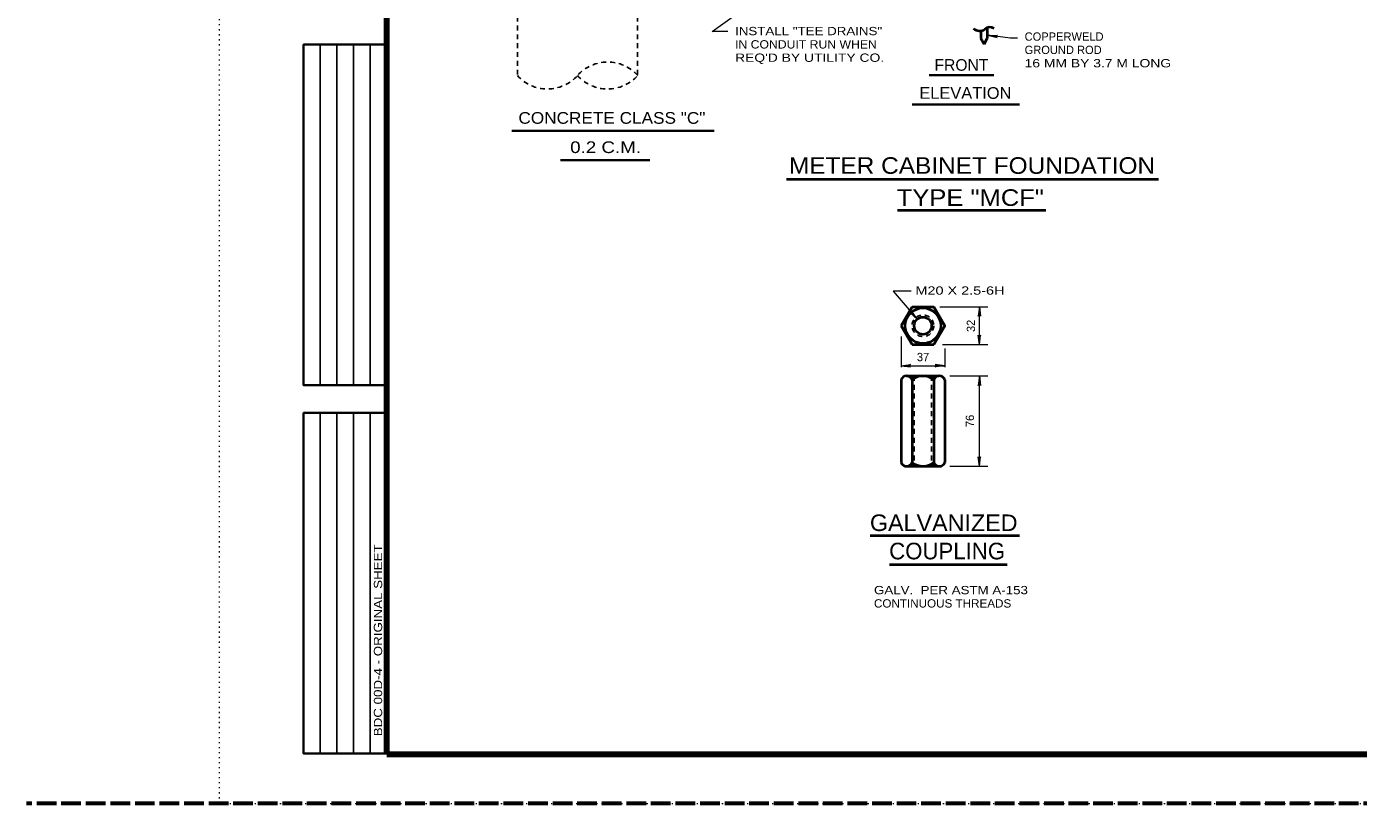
# Model space of a CAD drawing. Extents: x 312583 to 312854, y 144419 to 144597.
# Drawn here: x 312583.5 to 312705.5, y 144418.6 to 144489.8 of the extents above; entities that cross this region are included whole.
import ezdxf
from ezdxf.enums import TextEntityAlignment as Align

# ---------------------------------------------------------------- set-up
doc = ezdxf.new("R2010")
doc.units = 0
doc.header["$LTSCALE"] = 0.3
for name, pattern in [('DOTTED', [1.5, 0.3, -1.2]), ('LONG_DASHED', [7.5, 6, -1.5]), ('SHORT_DASHED', [2.7, 1.5, -1.2])]:
    doc.linetypes.add(name, pattern=pattern)
for name, color, linetype, lineweight in [('1', 7, 'Continuous', 25), ('2', 7, 'Continuous', 13), ('62', 7, 'DOTTED', 13), ('63', 7, 'LONG_DASHED', 60)]:
    doc.layers.add(name, color=color, linetype=linetype, lineweight=lineweight)

msp = doc.modelspace()

# ---------------------------------------------------------------- linework, layer by layer
at = {"layer": '1', "lineweight": 40}
for p, q in [((312670.8996, 144489.375), (312670.8996, 144488.6773)), ((312671.4976, 144489.6586), (312671.4976, 144488.6773)), ((312663.6128, 144462.3613), (312664.6095, 144464.0863)), ((312664.6095, 144464.0863), (312666.6028, 144464.0863)), ((312664.6095, 144460.6363), (312663.6128, 144462.3613)), ((312664.6095, 144460.6363), (312666.6028, 144460.6363)), ((312664.1111, 144457.7537), (312667.0551, 144457.7537)), ((312663.6128, 144457.4087), (312663.6128, 144449.8187)), ((312664.6171, 144457.4087), (312664.6171, 144449.8187)), ((312666.6028, 144457.4087), (312666.6028, 144449.8187)), ((312667.5995, 144457.4087), (312667.5995, 144449.8187)), ((312664.1111, 144449.4737), (312667.0551, 144449.4737)), ((312664.1111, 144449.4737), (312667.0551, 144449.4737))]:
    msp.add_line(p, q, dxfattribs=at)
at = {"layer": '1'}
for p, q in [((312610.4087, 144456.901), (312610.4087, 144488.1192)), ((312611.9315, 144456.901), (312611.9315, 144488.1192)), ((312613.4543, 144456.901), (312613.4543, 144488.1192)), ((312614.9772, 144456.901), (312614.9772, 144488.1192)), ((312610.4087, 144423.1446), (312610.4087, 144454.3629)), ((312611.9315, 144423.1446), (312611.9315, 144454.3629)), ((312613.4543, 144423.1446), (312613.4543, 144454.3629)), ((312614.9772, 144423.1446), (312614.9772, 144454.3629))]:
    msp.add_line(p, q, dxfattribs=at)
at = {"layer": '1', "linetype": 'SHORT_DASHED'}
for p, q in [((312664.8088, 144457.7537), (312664.8088, 144449.4737)), ((312666.4035, 144457.7537), (312666.4035, 144449.4737))]:
    msp.add_line(p, q, dxfattribs=at)
at = {"layer": '1', "lineweight": 158}
msp.add_line((312616.5, 144423.0846), (312849, 144423.0846), dxfattribs=at)
msp.add_lwpolyline([(312616.5, 144423.1446), (312616.5, 144585.0846), (312849, 144585.0846)], dxfattribs=at)
at = {"layer": '1', "lineweight": 35}
for points in [[(312616.5, 144456.901), (312608.8858, 144456.901), (312608.8858, 144488.1192), (312616.5, 144488.1192)], [(312616.5, 144423.1446), (312608.8858, 144423.1446), (312608.8858, 144454.3629), (312616.5, 144454.3629)]]:
    msp.add_lwpolyline(points, dxfattribs=at)
at = {"layer": '1', "lineweight": 40}
for points in [[(312666.6028, 144460.6363), (312667.5995, 144462.3613), (312666.6028, 144464.0863)], [(312664.2645, 144457.746), (312665.3378, 144457.7537), (312665.1155, 144457.7), (312664.8625, 144457.5927), (312664.6325, 144457.4393), (312664.5481, 144457.5543), (312664.4485, 144457.6617), (312664.3258, 144457.723), (312665.1768, 144457.7383), (312664.9775, 144457.677), (312664.8088, 144457.5773), (312664.6401, 144457.4777), (312664.5788, 144457.5467), (312664.4561, 144457.6693), (312664.3948, 144457.7), (312665.0618, 144457.723), (312664.6478, 144457.5083), (312664.4868, 144457.6693), (312664.9698, 144457.7), (312664.6478, 144457.539), (312664.5405, 144457.6617), (312664.8931, 144457.6847), (312664.6555, 144457.5697), (312664.5941, 144457.6463), (312664.7628, 144457.654), (312664.6555, 144457.608), (312664.6555, 144457.6463), (312664.7168, 144457.6387)], [(312666.9478, 144457.746), (312665.8821, 144457.7537), (312666.1045, 144457.7), (312666.3498, 144457.5927), (312666.5875, 144457.4393), (312666.6718, 144457.5543), (312666.7715, 144457.6617), (312666.8865, 144457.723), (312666.0355, 144457.7383), (312666.2348, 144457.677), (312666.4035, 144457.5773), (312666.5721, 144457.4777), (312666.6335, 144457.5467), (312666.7561, 144457.6693), (312666.8175, 144457.7), (312666.1581, 144457.723), (312666.5721, 144457.5083), (312666.7331, 144457.6693), (312666.2501, 144457.7), (312666.5721, 144457.539), (312666.6718, 144457.6617), (312666.3268, 144457.6847), (312666.5645, 144457.5697), (312666.6181, 144457.6463), (312666.4571, 144457.654), (312666.5568, 144457.608), (312666.5645, 144457.6463), (312666.4955, 144457.6387)], [(312664.2645, 144449.489), (312665.3378, 144449.4813), (312665.1155, 144449.535), (312664.8625, 144449.6423), (312664.6325, 144449.7957), (312664.5481, 144449.6807), (312664.4485, 144449.5733), (312664.3258, 144449.5043), (312665.1768, 144449.4967), (312664.9775, 144449.558), (312664.8088, 144449.65), (312664.6401, 144449.7497), (312664.5788, 144449.6807), (312664.4561, 144449.5657), (312664.3948, 144449.535), (312665.0618, 144449.512), (312664.6478, 144449.7267), (312664.4868, 144449.5657), (312664.9698, 144449.535), (312664.6478, 144449.696), (312664.5405, 144449.5733), (312664.8931, 144449.5503), (312664.6555, 144449.6653), (312664.5941, 144449.581), (312664.7628, 144449.581), (312664.6555, 144449.627), (312664.6555, 144449.581), (312664.7168, 144449.5963)], [(312666.9478, 144449.489), (312665.8821, 144449.4813), (312666.1045, 144449.535), (312666.3498, 144449.6423), (312666.5875, 144449.7957), (312666.6718, 144449.6807), (312666.7715, 144449.5733), (312666.8865, 144449.5043), (312666.0355, 144449.4967), (312666.2348, 144449.558), (312666.4035, 144449.65), (312666.5721, 144449.7497), (312666.6335, 144449.6807), (312666.7561, 144449.5657), (312666.8175, 144449.535), (312666.1581, 144449.512), (312666.5721, 144449.7267), (312666.7331, 144449.5657), (312666.2501, 144449.535), (312666.5721, 144449.696), (312666.6718, 144449.5733), (312666.3268, 144449.5503), (312666.5645, 144449.6653), (312666.6181, 144449.581), (312666.4571, 144449.581), (312666.5568, 144449.627), (312666.5645, 144449.581), (312666.4955, 144449.5963)]]:
    msp.add_lwpolyline(points, dxfattribs=at)
for radius in [1.6267, 0.7949]:
    msp.add_circle((312665.6072, 144462.3583), radius, dxfattribs=at)
at = {"layer": '1', "linetype": 'SHORT_DASHED'}
msp.add_circle((312665.6072, 144462.3583), 0.9936, dxfattribs=at)
at = {"layer": '1', "lineweight": 40}
for centre, radius, start, end in [((312670.8004, 144490.1751), 0.8027, 225.84295, 305.84934), ((312671.7467, 144488.9938), 0.713, 58.11032, 131.90694), ((312664.114, 144457.223), 0.5342, 20.74148, 159.25852), ((312665.6072, 144456.1539), 1.6033, 51.70372, 128.29627), ((312667.1003, 144457.223), 0.5342, 20.74148, 159.25852), ((312664.114, 144450.0113), 0.5342, 200.74148, 339.25852), ((312665.6072, 144451.0804), 1.6033, 231.70372, 308.29627), ((312667.1003, 144450.0113), 0.5342, 200.74148, 339.25852)]:
    msp.add_arc(centre, radius, start, end, dxfattribs=at)
at = {"layer": '1', "linetype": 'SHORT_DASHED'}
for centre, start, end in [((312636.7283, 144482.8473), 41.50958, 138.49042), ((312631.2179, 144487.7242), 221.50958, 318.49042), ((312636.7283, 144487.7242), 221.50958, 318.49042)]:
    msp.add_arc(centre, 3.6793, start, end, dxfattribs=at)
at = {"layer": '2', "linetype": 'SHORT_DASHED', "lineweight": 25}
for p, q in [((312628.4646, 144517.4043), (312628.4646, 144485.2886)), ((312639.4816, 144517.4043), (312639.4816, 144485.2886))]:
    msp.add_line(p, q, dxfattribs=at)
at = {"layer": '2'}
for p, q in [((312646.2896, 144489.329), (312651.1273, 144492.802)), ((312647.7463, 144489.329), (312646.2896, 144489.329)), ((312671.559, 144488.9686), (312672.4023, 144488.754)), ((312671.559, 144488.9686), (312672.433, 144488.961)), ((312672.433, 144488.961), (312672.1493, 144488.892)), ((312672.4023, 144488.754), (312672.1493, 144488.892)), ((312664.4408, 144463.542), (312664.7015, 144463.404)), ((312665.0848, 144462.9593), (312664.4408, 144463.542)), ((312664.6018, 144463.6877), (312664.7015, 144463.404)), ((312665.0848, 144462.9593), (312664.6018, 144463.6877)), ((312667.1471, 144464.0863), (312671.5555, 144464.0863)), ((312670.7735, 144464.0863), (312670.6661, 144463.22)), ((312670.7735, 144460.6363), (312670.7735, 144464.0863)), ((312670.7735, 144464.0863), (312670.8808, 144463.22)), ((312670.6661, 144463.22), (312670.7735, 144463.496)), ((312670.8808, 144463.22), (312670.7735, 144463.496)), ((312663.6128, 144461.3723), (312663.6128, 144458.5587)), ((312670.6661, 144461.5027), (312670.7735, 144461.2267)), ((312670.7735, 144460.6363), (312670.6661, 144461.5027)), ((312670.8808, 144461.5027), (312670.7735, 144461.2267)), ((312670.7735, 144460.6363), (312670.8808, 144461.5027)), ((312667.4001, 144460.6363), (312671.5555, 144460.6363)), ((312667.5995, 144460.2837), (312667.5995, 144458.5663)), ((312663.6128, 144458.689), (312664.4791, 144458.7963)), ((312663.6128, 144458.689), (312667.5995, 144458.689)), ((312663.6128, 144458.689), (312664.4791, 144458.5817)), ((312664.4791, 144458.7963), (312664.2031, 144458.689)), ((312664.4791, 144458.5817), (312664.2031, 144458.689)), ((312666.7331, 144458.7963), (312667.0091, 144458.689)), ((312667.5995, 144458.689), (312666.7331, 144458.7963)), ((312666.7331, 144458.5817), (312667.0091, 144458.689)), ((312667.5995, 144458.689), (312666.7331, 144458.5817)), ((312668.0748, 144457.7537), (312671.5555, 144457.7537)), ((312670.7735, 144457.7537), (312670.6661, 144456.8873)), ((312670.7735, 144449.4737), (312670.7735, 144457.7537)), ((312670.7735, 144457.7537), (312670.8808, 144456.8873)), ((312670.6661, 144456.8873), (312670.7735, 144457.1633)), ((312670.8808, 144456.8873), (312670.7735, 144457.1633)), ((312670.6661, 144450.34), (312670.7735, 144450.064)), ((312670.7735, 144449.4737), (312670.6661, 144450.34)), ((312670.8808, 144450.34), (312670.7735, 144450.064)), ((312670.7735, 144449.4737), (312670.8808, 144450.34)), ((312668.0748, 144449.4737), (312671.5555, 144449.4737))]:
    msp.add_line(p, q, dxfattribs=at)
at = {"layer": '2', "lineweight": 40}
for p, q in [((312671.1986, 144488.156), (312670.8996, 144488.6773)), ((312671.1986, 144488.156), (312671.4976, 144488.6773)), ((312653.1206, 144475.7859), (312687.188, 144475.7859)), ((312663.2685, 144472.9561), (312676.8636, 144472.9561)), ((312660.7709, 144443.1278), (312674.4564, 144443.1278)), ((312662.531, 144440.4675), (312673.3069, 144440.4675))]:
    msp.add_line(p, q, dxfattribs=at)
at = {"layer": '2', "lineweight": 35}
for p, q in [((312666.1749, 144485.315), (312672.0837, 144485.315)), ((312664.6124, 144482.6187), (312674.4544, 144482.6187)), ((312627.9665, 144480.2056), (312646.5012, 144480.2056)), ((312632.4206, 144477.5223), (312640.6103, 144477.5223))]:
    msp.add_line(p, q, dxfattribs=at)
at = {"layer": '2'}
for points in [[(312674.2576, 144488.708), (312673.583, 144488.708), (312671.559, 144488.9686)], [(312664.5251, 144465.52), (312662.8691, 144465.52), (312665.0848, 144462.9593)]]:
    msp.add_lwpolyline(points, dxfattribs=at)
at = {"layer": '62'}
msp.add_line((312601.2, 144418.5846), (312601.2, 144596.7846), dxfattribs=at)
msp.add_lwpolyline([(312601.2, 144418.5846), (312853.5, 144418.5846), (312853.5, 144596.7846)], dxfattribs=at)
at = {"layer": '63'}
msp.add_line((312851.75, 144418.5846), (312583.526, 144418.5846), dxfattribs=at)

# ---------------------------------------------------------------- texts
at = {"layer": '1', "width": 1.2}
msp.add_text('BDC 00D-4 - ORIGINAL SHEET', height=0.7614, rotation=90, dxfattribs=at).set_placement((312616.0832, 144424.7374))
at = {"layer": '2'}
for s, width, p in [('INSTALL "TEE DRAINS"', 1.2, (312648.4017, 144488.9801)), ('IN CONDUIT RUN WHEN', 1.1, (312648.4017, 144487.7601)), ("REQ'D BY UTILITY CO.", 1.25, (312648.4017, 144486.5401)), ('16 MM BY 3.7 M LONG', 1.25, (312674.9179, 144486.0341)), ('M20 X 2.5-6H', 1.3, (312664.9202, 144465.2025)), ('GALV.  PER ASTM A-153', 1.2, (312661.1228, 144437.751)), ('CONTINUOUS THREADS', 1.05, (312661.1228, 144436.531))]:
    msp.add_text(s, height=0.76, dxfattribs=dict(at, width=width)).set_placement(p)
for s, p in [('COPPERWELD', (312674.9179, 144488.4741)), ('GROUND ROD', (312674.9179, 144487.2541)), ('37', (312665.0502, 144459.108))]:
    msp.add_text(s, height=0.76, dxfattribs=at).set_placement(p)
for s, height, p in [('FRONT', 1.07, (312669.1325, 144485.7196)), ('COUPLING', 1.52, (312667.8215, 144440.9488))]:
    msp.add_text(s, height=height, dxfattribs=at).set_placement(p, align=Align.CENTER)
for s, height, width, p in [('ELEVATION', 1.07, 1.05, (312669.491, 144483.1513)), ('CONCRETE CLASS "C"', 1.07, 1.1, (312637.1218, 144480.8639)), ('0.2 C.M.', 1.07, 1.2, (312636.5438, 144478.1806)), ('METER CABINET FOUNDATION', 1.52, 1.1, (312670.099, 144476.2766)), ('TYPE "MCF"', 1.52, 1.15, (312669.9453, 144473.3389)), ('GALVANIZED', 1.52, 1.05, (312667.5099, 144443.5401))]:
    msp.add_text(s, height=height, dxfattribs=dict(at, width=width)).set_placement(p, align=Align.CENTER)
for s, p in [('32', (312670.3756, 144461.7749)), ('76', (312670.2832, 144453.0672))]:
    msp.add_text(s, height=0.76, rotation=90, dxfattribs=at).set_placement(p)

doc.saveas('drawing.dxf')
